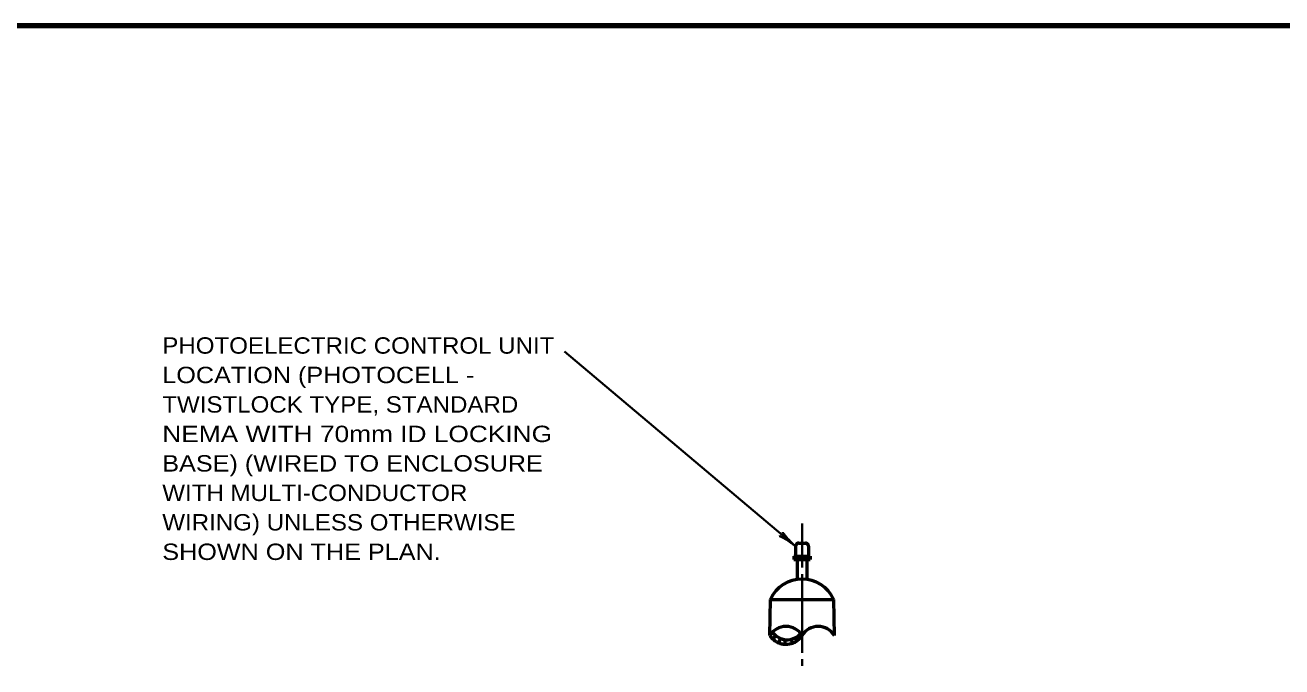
# Model space of a CAD drawing. Extents: x -111 to 744, y -77 to 467.
# Drawn here: x 90.6 to 320.8, y 342.7 to 460.3 of the extents above; entities that cross this region are included whole.
import ezdxf

# ---------------------------------------------------------------- set-up
doc = ezdxf.new("R2010")
doc.units = 0
doc.header["$LTSCALE"] = 1.2
doc.layers.add('1', color=7, linetype='Continuous', lineweight=53)

msp = doc.modelspace()

# ---------------------------------------------------------------- linework, layer by layer
at = {"layer": '1', "lineweight": 35}
for p, q in [((231.739, 364.767), (189.403, 400.461)), ((232.939, 368.966), (232.939, 363.28)), ((232.939, 362.079), (232.939, 360.88)), ((232.939, 359.68), (232.939, 345.28)), ((232.939, 344.079), (232.939, 342.88))]:
    msp.add_line(p, q, dxfattribs=at)
at = {"layer": '1'}
for p, q in [((231.739, 364.767), (231.739, 362.966)), ((232.339, 365.367), (233.539, 365.367)), ((234.139, 364.767), (234.139, 362.966)), ((231.439, 362.966), (234.439, 362.966)), ((231.439, 362.966), (231.439, 362.367)), ((231.439, 362.367), (234.439, 362.367)), ((232.039, 362.367), (232.039, 358.703)), ((233.839, 362.367), (233.839, 358.703)), ((234.439, 362.966), (234.439, 362.367)), ((227.026, 348.449), (227.136, 355.048)), ((227.136, 355.048), (238.742, 355.048)), ((238.852, 348.449), (238.742, 355.048)), ((228.14, 348.367), (227.556, 347.796)), ((228.703, 347.058), (229, 347.871)), ((230.82, 347.705), (231.233, 347.046)), ((232.031, 347.479), (231.623, 347.971)), ((232.374, 348.469), (232.728, 348.149)), ((229.868, 347.662), (229.706, 346.826))]:
    msp.add_line(p, q, dxfattribs=at)
at = {"layer": '1', "lineweight": 158}
msp.add_lwpolyline([(737.728, 460.265), (-53.972, 460.165), (-53.872, -65.835)], dxfattribs=at)
at = {"layer": '1'}
for centre, radius, start, end in [((232.339, 364.767), 0.6, 90, 180), ((233.539, 364.767), 0.6, 0, 90), ((232.939, 352.379), 6.388, 24.70337, 155.29762), ((229.982, 346.593), 3.491, 32.12603, 147.87591), ((235.895, 346.593), 3.491, 32.12603, 147.87591), ((229.982, 346.593), 3.491, 135.28632, 147.87591), ((229.982, 350.306), 3.491, 212.12419, 248.50023), ((229.982, 350.306), 3.491, 212.12409, 225.97386), ((230.197, 350.935), 3.29, 214.99106, 264.27121), ((230.197, 350.935), 3.29, 214.99106, 231.31632), ((230.197, 350.935), 3.29, 248.66508, 264.27128), ((230.197, 350.935), 3.29, 264.27128, 295.69699), ((230.197, 350.935), 3.29, 280.91416, 295.69709), ((229.982, 350.306), 3.491, 290.98858, 321.84618), ((230.197, 350.935), 3.29, 295.69709, 319.35845), ((230.197, 350.935), 3.29, 311.43068, 319.35845), ((229.982, 346.593), 3.491, 32.12603, 39.06319), ((229.982, 350.306), 3.491, 321.84618, 327.87397), ((229.982, 350.306), 3.491, 248.50024, 290.98876), ((229.982, 350.306), 3.491, 248.50023, 265.46761), ((229.982, 350.306), 3.491, 290.98876, 305.93139)]:
    msp.add_arc(centre, radius, start, end, dxfattribs=at)
at = {"layer": '1', "lineweight": 40}
for centre, major_axis, ratio, start_param, end_param in [((230.524, 365.357), (1.759, -1.238), 0.122415, 0.8963533, 3.1415927), ((230.875, 365.827), (1.476, -1.52), 0.07063, 3.1407148, 5.41811)]:
    msp.add_ellipse(centre, major_axis=major_axis, ratio=ratio, start_param=start_param, end_param=end_param, dxfattribs=at)

# ---------------------------------------------------------------- texts
at = {"layer": '1'}
for s, width, p in [('PHOTOELECTRIC CONTROL UNIT', 1.1, (115.719, 400.067)), ('LOCATION (PHOTOCELL -', 1.15, (115.719, 394.668)), ('TWISTLOCK TYPE, STANDARD', 1.1, (115.719, 389.268)), ('NEMA WITH 70mm ID LOCKING', 1.2, (115.719, 383.868)), ('BASE) (WIRED TO ENCLOSURE', 1.15, (115.719, 378.468)), ('WITH MULTI-CONDUCTOR', 1.1, (115.719, 373.067)), ('WIRING) UNLESS OTHERWISE', 1.1, (115.719, 367.668)), ('SHOWN ON THE PLAN.', 1.15, (115.719, 362.268))]:
    msp.add_text(s, height=3, dxfattribs=dict(at, width=width)).set_placement(p)

doc.saveas('drawing.dxf')
